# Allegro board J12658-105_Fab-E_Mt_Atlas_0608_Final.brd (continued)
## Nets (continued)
GND: C1.2(B) C2.2(B) C3.2(B) C4.2(B) C5.2(B) C6.2(B) C7.2(B) C8.2(B) C9.2(B) C10.2(B) C11.2(B) C12.2(B) C13.2(B) C14.2(B) C15.2(B) C16.2(B) C17.2(B) C18.2(B) C19.2(B) C20.2(B) C21.2(B) C22.2(B) C23.2(B) C24.2(B) C25.2(B) C26.2(B) C27.2(B) C28.2(B) C29.2(B) C30.2(B) C31.2(B) C32.2(B) C33.2(B) C34.2(B) C35.2(B) C36.2(B) C37.2(B) C38.2(B) C39.2(B) C40.2(B) C41.2(B) C42.2(B) C43.2(B) C44.2(B) C45.2(B) C46.2(B) C47.2(B) C48.2(B) C49.2(B) C50.2(B) C51.2(B) C52.2(B) C53.2(B) C54.2(B) C55.2(B) C56.2(B) C57.2(B) C58.2(B) C59.2(B) C60.2(B) C61.2(B) C62.2(B) C63.2(B) C64.2(B) C65.2(B) C66.2(B) C67.2(B) C68.2(B) C69.2(B) C70.2(B) C71.2(B) C72.2(B) C73.2(B) C74.2(B) C75.2(B) C76.2(B) C77.2(B) C78.2(B) C79.2(B) C80.2(B) C81.2(B) C82.2(B) C83.2(B) C84.2(B) C85.2(B) C86.2(B) C87.2(B) C88.2(B) C89.2(B) C90.2(B) C91.2(B) C92.2(B) C93.2(B) C94.2(B) C95.2(B) C96.2(B) C97.2(B) C98.2(B) C99.2(B) C100.2(B) C101.2(B) C102.2(B) C103.2(B) C104.2(B) C105.2(B) FL1.2(GND0) FL1.3(GND1) FL1.5(GND2) HW1.1(GND) HW1.2(GND1) HW1.3(GND2) HW1.4(GND3) HW1.5(GND4) HW1.6(GND5) HW1.7(GND6) HW1.8(GND7) J1.5 J1.6(SHIELD6) J1.7(SHIELD7) J1.8(SHIELD8) J1.9(SHIELD9) J1.10(SHIELD10) J1.11(SHIELD111) J2.5 J2.6(SHIELD6) J2.7(SHIELD7) J2.8(SHIELD8) J2.9(SHIELD9) J2.10(SHIELD10) J2.11(SHIELD111) J4.1(IO1) J6.3 J8.4 J9.6 J9.7 J10.3 J10.5 J10.9 J13.2(SHLD1) J13.3(SHLD2) J14.11 J14.12 J14.33 J14.40 J15.17 J15.18 J15.43 J15.44 J20.1 J21.1 MH1.1 MH2.1 MH3.1 MH4.1 Q1.2 Q2.2 Q4.2 Q5.2 R1.2(B) R4.2(B) R6.2(B) R11.2(B) R17.2(B) R61.2(B) R87.2(B) R91.2(B) R97.2(B) R102.2(B) R110.2(B) R122.2(B) R123.2(B) R130.2(B) R141.2(B) R142.2(B) R144.2(B) R146.2(B) R148.2(B) R151.2(B) R167.2(B) R171.2(B) R188.2(B) R192.2(B) R199.2(B) R204.2(B) R257.2(B) R262.1(A) R274.2(B) R276.2(B) R280.2(B) R283.2(B) R284.2(B) RF1.2 RF1.5 RF1.6 S1.1 SW1.1 SW2.1 SW4.5 U1.5(GND) U1.7(THPAD) U2.5(GND) U2.7(THPAD) U3.2(GND) U4.2(GND) U5.2(GND) U6.2(VSS) U7.B1(GND) U8.8(GND) U9.10(GND1) U9.11(GND2) U10.2(GND) U10.3(A0) U10.7(EP) U11.9(GND_1) U11.18(GND_2) U11.25(GND_3) U11.34(GND_4) U11.45(AGND) U11.47(TEST) U12.1(A0) U12.2(A1) U12.3(A2) U12.4(VSS) U12.7(WP) U12.9(EP) U13.10(GND1) U13.11(GND2) U14.6(GNDIO) U14.7(GND) U15.4(GND) U15.9(SLUG) U16.2(GND) U16.5(PAD) U17.10(GND1) U17.11(GND2) U18.8(GND) U19.8(GND) U19.15(OE*) U20.8(GND) U20.15(OE*) U21.2(GND) U22.A1(VSS) U22.A12(VSS1) U22.E7(VSS2) U22.F7(VSS3) U22.F8(VSS_RTC) U22.G6(VSS_IO_AON1) U22.G7(VSS4) U22.H6(VSS_GNDSENSE_ESR1) U22.H8(VSS5) U22.J2(VSS_GNDSENSE_ESR2) U22.J3(VSS_AVS_ESR2) U22.J6(VSS_AVS_ESR1) U22.J8(VSS_AVS_ESR3) U22.J9(VSS6) U22.J10(VSS_IO_AON) U22.J11(VSS_USB) U22.J12(VSS_PLL) U22.L3(VSS_GNDSENSE_OPM) U22.L8(VSS_AVSS_CMP) U22.M1(VSS7) U22.M7(VSS_GNDSENSE_ESR3) U22.M9(VSS_AVSS_CMP1) U22.M12(VSS8) U23.8(GND) U23.15(OE*) U24.2(GND) U25.8(GND) U25.15(OE*) U26.3(GND) U27.2(GND) U28.8(GND) U28.15(OE*) U29.29(PAD) U30.1(GND1) U30.2(GND2) U30.13(GND13) U30.25(GND25) U30.42(GND42) U31.3(GND) U31.5(DIE) U32.4(GND) U33.2(GND) U36.2(GND) U37.2(GND) U38.2(GND) U39.3(GND) U40.3(PGND) U40.9(GND) U40.11(THPAD) Y2.2(GND0) Y2.4(GND1) Y4.2(GND0) Y4.4(GND1)
VBAT_SOC: C27.1(A) C30.1(A) C83.1(A) FB11.2(B) U22.K2(VCC_BATT_ESR2_3P7) U22.L1(VCC_BATT_OPM_3P7) U22.L2(VCC_BATT_ESR3_3P7) U22.M2(VCC_BATT_ESR1_3P7)
VCC_ADC: C23.1(A) C77.1(A) FB16.2(B) U22.M10(VCC_ADC_3P3)
VCC_AON_1P8: C82.1(A) C92.1(A) C93.1(A) U22.H4(VCC_AON_1P8) U22.H5(VCC_AON_1P8_1) U22.J4(VCC_RTC_1P8) U22.J5(VCC_SRAM_1P8) U27.5(OUT)
VCC_AON_EN: R215.2(B) U27.3(EN)
VCC_ARD_USB_5V: D6.1(CATHODE) D7.1(CATHODE) FB12.1(A) J5.1
VCC_AVD_OPM_2P6: C85.1(A) C88.1(A) U22.J1(VCCOUT_AVD_OPM_2P6) U22.K1(VCC_AVD_OPM_2P6)
VCC_CMP: C24.1(A) C78.1(A) R64.1(A) R272.2(B) U22.M8(VCC_CMP_3P3)
VCC_EX_HOST_1P8: C9.1(A) FB8.2(B) R10.1(A)
VCC_EX_PLT_1P8: C86.1(A) FB9.2(B) U8.3(D1)
VCC_EX_PLT_3P3: C76.1(A) FB7.2(B) R64.2(B) U18.3(D1)
VCC_HOST_1P8: C20.1(A) C81.1(A) FB8.1(A) L4.2 R5.1(A) R213.1(A) U22.H7(VCC_PLL_1P8) U22.J7(VCC_HOST_1P8) U22.K6(VCCOUT_HOST_1P8) U22.K7(VCC_HOST_1P8_1) U22.L6(VCC_VSENSE_ESR3) U22.L7(VCC_HOST_1P8_2)
VCC_HOST_1P8_IND: L4.1 U22.M6(VCCOUT_ESR3_1P8)
VCC_IO: C26.1(A) C28.1(A) C29.1(A) C60.1(A) C64.1(A) C67.1(A) C68.1(A) C70.1(A) C73.1(A) C80.1(A) C89.1(A) FB6.1(A) FB14.1(A) FB15.1(A) J10.1 R52.1(A) R66.2(B) R129.1(A) R134.1(A) R137.1(A) R150.1(A) R152.1(A) R153.1(A) R157.1(A) R159.1(A) R163.1(A) R165.1(A) R170.1(A) R172.1(A) R173.1(A) R174.1(A) R175.1(A) R176.1(A) R177.1(A) R178.1(A) R179.1(A) R180.1(A) R181.1(A) R182.1(A) R185.1(A) R187.1(A) R189.1(A) R190.1(A) R191.1(A) R193.1(A) R194.1(A) R197.1(A) R200.1(A) R201.1(A) R202.1(A) R203.1(A) R205.1(A) R206.1(A) R207.1(A) R209.1(A) R210.1(A) R211.1(A) R212.1(A) R232.1(A) R237.1(A) R246.1(A) R249.1(A) R275.1(A) R277.1(A) R282.1(A) U9.2(VCCB) U10.1(VCC) U12.8(VCC) U13.2(VCCB) U15.8(VDD) U17.2(VCCB) U19.16(VCC) U20.16(VCC) U21.5(VIN) U23.16(VCC) U25.16(VCC) U28.16(VCC) U32.8(VCC) U33.5(VCC) U36.6(VCCB) U38.5(VCC)
VCC_IO_AON: C22.1(A) C79.1(A) C102.1(A) R57.2(B) U22.F6(VCC_IO_AON1) U22.G8(VCC_IO_AON2) U22.H10(VCC_IO_AON) U26.4(VDD)
VCC_PLT: FB16.1(A) R57.1(A) R66.1(A) U8.6(S1) U18.6(S1)
VCC_PLT_1P8: C21.1(A) C87.1(A) FB9.1(A) L6.2 U22.K4(VCCOUT_QLR2_1P8) U22.L4(VCC_VSENSE_ESR2)
VCC_PLT_1P8_IND: L6.1 U22.M4(VCCOUT_ESR2_1P8)
VCC_PLT_3P3: C19.1(A) C63.1(A) FB7.1(A) L5.2 U22.K5(VCCOUT_QLR1_3P3) U22.L5(VCC_VSENSE_ESR1)
VCC_PLT_3P3_IND: L5.1 U22.M5(VCCOUT_ESR1_3P3)
VCC_RADIO: C31.1(A) FB15.2(B) R84.1(A) R88.1(A) R99.1(A) R100.1(A) R101.1(A) R106.1(A) R107.1(A) R113.1(A) R114.1(A)
VCC_RST_GEN: R125.2(B) U31.4(VCC)
VCC_USB_3P3: C17.1(A) C18.1(A) C74.1(A) R278.1(A) U16.1(VOUT) U22.L12(VCC_USB_3P3)
VCCOUT_AON_1P8: C25.1(A) C84.1(A) R215.1(A) U22.M3(VCCOUT_AON_1P8)
VDD_ARDUINO: C44.1(A) C46.1(A) FB10.1(A) R126.1(A) R272.1(A) U1.1(OUT)
VDD_ARDUINO_EN: R124.2(B) U1.4(EN)
VDD_ARDUINO_FB: R123.1(A) R126.2(B) U1.3(VSET_FB)
VDD_HDR: C47.1(A) C49.1(A) J14.1 J14.2 J14.23 J14.26 J14.49 J14.50 J15.1 J15.2 J15.29 J15.34 R132.1(A) U2.1(OUT)
VDD_HDR_EN: R131.2(B) U2.4(EN)
VDD_HDR_FB: R130.1(A) R132.2(B) R133.1(A) U2.3(VSET_FB)
VDD_IMU: C14.1(A) C15.1(A) FB6.2(B) R24.1(A) R28.1(A) U14.5(VDDIO) U14.8(VDD)
VDD_USB: C8.1(A) R273.1(A) U7.A1(VOUT)
VDD_USB_EN: C5.1(A) R10.2(B) U7.B2(ON)
VDD_USB_R: C98.1(A) R33.1(A) R273.2(B) U16.4(VIN)
15_4_GPIO0: R97.1(A) U29.10(GPIO0)
15_4_GPIO1: R83.2(B) R84.2(B) U29.9(GPIO1)
15_4_GPIO2: R98.2(B) R99.2(B) U29.7(GPIO2)
15_4_GPIO3: R85.2(B) R100.2(B) U29.6(GPIO3)
15_4_GPIO4: R86.2(B) R101.2(B) U29.5(GPIO4)
15_4_GPIO5: R87.1(A) U29.4(GPIO5)
15_4_RESET_N: R108.1(A) U32.3(2Y)
15_4_RESET_N_R: R108.2(B) U29.25(RESET*)
15_4_XIN: C40.1(A) U29.13(XOSC_Q1) Y4.3
15_4_XOUT: C37.1(A) U29.12(XOSC_Q2) Y4.1
A_3P3V: FB10.2(B) J9.4
A_5P0V: FB12.2(B) J9.5
A_VIN: FB13.2(B) J9.8
ADC_AGND: R192.1(A) U22.L10(VSS_ADC_AGND)
AMBIENT_INT_N: R150.2(B) U10.4(INT*)
AP_COMP_AREF: C75.1(A) R169.2(B) R170.2(B) R171.1(A) U22.H9(COMP_AREF)
AP_GPIO0_ADC0_SPI_S_CS_N: R178.2(B) R258.2(B) U22.D12(GPIO_0_AIN_0_SPI_S_CS_B)
AP_GPIO0_ADC0_SPI_S_CS_N_R_HDR: J15.42 R258.1(A)
AP_GPIO1_ADC1_SPI_S_MISO: R213.2(B) R242.2(B) U22.E10(GPIO_1_AIN_1_SPI_S_MISO) U28.13(4B2)
AP_GPIO1_ADC1_SPI_S_MISO_HDR: J15.38 R242.1(A)
AP_GPIO2_ADC2_SPI_S_SCK: R236.2(B) U22.E11(GPIO_2_AIN_2_SPI_S_SCK)
AP_GPIO2_ADC2_SPI_S_SCK_HDR: J15.36 R236.1(A)
AP_GPIO3_ADC3_SPI_S_MOSI: R251.2(B) U22.E12(GPIO_3_AIN_3_SPI_S_MOSI)
AP_GPIO3_ADC3_SPI_S_MOSI_HDR: J15.40 R251.1(A)
AP_GPIO4_ADC4: R38.1(A) R83.1(A) U22.F9(GPIO_4_AIN_4)
AP_GPIO4_ADC4_HDR: J14.13 R38.2(B)
AP_GPIO5_ADC5: R44.1(A) R98.1(A) U22.F10(GPIO_5_AIN_5)
AP_GPIO5_ADC5_HDR: J14.15 R44.2(B)
AP_GPIO6_ADC6: U22.L9(GPIO_6_AIN_6) U38.4(A)
AP_GPIO6_ADC6_HDR: J14.17 R47.2(B)
AP_GPIO6_ADC6_MUX: R47.1(A) R85.1(A) U38.1(B2)
AP_GPIO7_ADC7: R33.2(B) R199.1(A) R261.1(A) U22.K8(GPIO_7_AIN_7)
AP_GPIO7_ADC7_HDR: J14.47 R261.2(B)
AP_GPIO8_SPI1_M_SCK: R63.2(B) R96.1(A) R229.2(B) U22.D6(GPIO_8_SPI1_M_SCK)
AP_GPIO8_SPI1_M_SCK_BLE: R229.1(A) U30.12(P0.29/SCK)
AP_GPIO8_SPI1_M_SCK_HDR: J15.20 R63.1(A)
AP_GPIO8_SPI1_M_SCK_R: R96.2(B) U29.28(SCLK)
AP_GPIO9_SPI1_M_MISO: R73.2(B) R92.1(A) R228.2(B) U22.B6(GPIO_9_SPI1_M_MISO)
AP_GPIO9_SPI1_M_MISO_BLE: R228.1(A) U30.11(P0.28/MISO)
AP_GPIO9_SPI1_M_MISO_HDR: J15.22 R73.1(A)
AP_GPIO9_SPI1_M_MISO_R: R91.1(A) R92.2(B) U29.1(SO)
AP_GPIO10_SPI1_M_MOSI: R77.2(B) R90.1(A) R245.2(B) U22.A6(GPIO_10_SPI1_M_MOSI)
AP_GPIO10_SPI1_M_MOSI_BLE: R245.1(A) U30.8(P0.25/MOSI)
AP_GPIO10_SPI1_M_MOSI_HDR: J15.24 R77.1(A)
AP_GPIO10_SPI1_M_MOSI_R: R90.2(B) U29.2(SI)
AP_GPIO11_SPI1_M_CS0_N: R81.2(B) R89.1(A) R211.2(B) U22.C6(GPIO_11_SPI1_M_CS_B_0)
AP_GPIO11_SPI1_M_CS0_N_HDR: J15.26 R81.1(A)
AP_GPIO11_SPI1_M_CS0_N_R: R88.2(B) R89.2(B) U29.3(CS*)
AP_GPIO12_SPI1_M_CS1_N: R205.2(B) R216.2(B) R250.2(B) R263.1(A) U22.B5(GPIO_12_SPI1_M_CS_B_1)
AP_GPIO12_SPI1_M_CS1_N_BLE: R250.1(A) U30.7(P0.24/SS)
AP_GPIO12_SPI1_M_CS1_N_HDR: J15.28 R216.1(A)
AP_GPIO13_SPI1_M_CS2_N: R206.2(B) R214.1(A) R219.2(B) U22.A5(GPIO_13_SPI1_M_CS_B_2)
AP_GPIO13_SPI1_M_CS2_N_HDR: J15.30 R219.1(A)
AP_GPIO14_SPI1_M_CS3_N: C104.1(A) R135.2(B) R210.2(B) R222.2(B) U22.D5(GPIO_14_SPI1_M_CS_B_3)
AP_GPIO14_SPI1_M_CS3_N_HDR: J15.32 R222.1(A)
AP_GPIO15_I2S_RXD: R67.2(B) U22.C5(GPIO_15_I2S_RXD) U25.3(1B2)
AP_GPIO15_I2S_RXD_HDR: J14.28 R67.1(A)
AP_GPIO16_I2S_RSCK: R80.2(B) U22.B4(GPIO_16_I2S_RSCK) U28.3(1B2)
AP_GPIO16_I2S_RSCK_HDR: J14.30 R80.1(A)
AP_GPIO17_I2S_RWS: R94.2(B) U22.D4(GPIO_17_I2S_RWS) U25.6(2B2)
AP_GPIO17_I2S_RWS_HDR: J14.32 R94.1(A)
AP_GPIO18_I2S_TSCK: R218.2(B) U22.A4(GPIO_18_I2S_TSCK) U28.6(2B2)
AP_GPIO18_I2S_TSCK_HDR: J14.34 R218.1(A)
AP_GPIO19_I2S_TWS: R224.2(B) U22.C4(GPIO_19_I2S_TWS) U28.10(3B2)
AP_GPIO19_I2S_TWS_HDR: J14.36 R224.1(A)
AP_GPIO20_I2S_TXD: R233.2(B) U22.B3(GPIO_20_I2S_TXD) U25.10(3B2)
AP_GPIO20_I2S_TXD_HDR: J14.38 R233.1(A)
AP_GPIO21_SPI0_M_SCK: R20.2(B) U15.6(CLK) U22.A3(GPIO_21_SPI0_M_SCK) U23.13(4B2)
AP_GPIO21_SPI0_M_SCK_HDR: J15.4 R20.1(A)
AP_GPIO22_SPI0_M_MISO: R27.2(B) U15.2(DO/1O1) U22.C3(GPIO_22_SPI0_M_MISO) U23.10(3B2)
AP_GPIO22_SPI0_M_MISO_HDR: J15.6 R27.1(A)
AP_GPIO23_SPI0_M_MOSI: R35.2(B) U15.5(IO0/DI) U22.D3(GPIO_23_SPI0_M_MOSI) U23.6(2B2)
AP_GPIO23_SPI0_M_MOSI_HDR: J15.8 R35.1(A)
AP_GPIO24_SPI0_M_CS0_N: R39.2(B) R159.2(B) U15.1(CE*) U22.E4(GPIO_24_SPI0_M_CS_B_0)
AP_GPIO24_SPI0_M_CS0_N_HDR: J15.10 R39.1(A)
AP_GPIO25_SPI0_M_CS1_N: Q4.1 R43.2(B) R209.2(B) U22.E3(GPIO_25_SPI0_M_CS_B_1)
AP_GPIO25_SPI0_M_CS1_N_HDR: J15.12 R43.1(A)
AP_GPIO26_SPI0_M_CS2_N: Q5.1 R48.2(B) R212.2(B) U22.B2(GPIO_26_SPI0_M_CS_B_2)
AP_GPIO26_SPI0_M_CS2_N_HDR: J15.14 R48.1(A)
AP_GPIO27_SPI0_M_CS3_N: R207.2(B) U22.A2(GPIO_27_SPI0_M_CS_B_3) U33.4(A)
AP_GPIO27_SPI0_M_CS3_N_HDR: J15.16 R54.1(A)
AP_GPIO27_SPI0_M_CS3_N_MUX: R54.2(B) U23.3(1B2) U33.1(B2)
AP_GPIO28: R61.1(A) U16.3(EN) U22.C2(GPIO_28)
AP_GPIO_AON0: R105.1(A) R221.1(A) U22.F3(GPIO_AON_0)
AP_GPIO_AON0_HDR: J14.35 R221.2(B)
AP_GPIO_AON0_R: R102.1(A) R105.2(B) R106.2(B) U29.26(VREG_EN)
AP_GPIO_AON1: R226.1(A) U22.F5(GPIO_AON_1) U32.6(2B)
AP_GPIO_AON1_HDR: J14.37 R226.2(B)
AP_GPIO_AON2: R235.1(A) U22.F4(GPIO_AON_2) U32.1(1A)
AP_GPIO_AON2_HDR: J14.39 R235.2(B)
AP_GPIO_AON3: R183.1(A) R240.1(A) U22.F2(GPIO_AON_3)
AP_GPIO_AON3_HDR: J14.41 R240.2(B)
AP_GPIO_AON4: C105.1(A) R136.2(B) R247.1(A) U22.F1(GPIO_AON_4)
AP_GPIO_AON4_HDR: J14.43 R247.2(B)
AP_GPIO_AON5: R195.1(A) R255.1(A) U22.E6(GPIO_AON_5)
AP_GPIO_AON5_HDR: J14.45 R255.2(B)
AP_GPIO_SS0_ADC8_UART1_CTS_N: R174.2(B) U20.9(3A) U22.F11(GPIO_SS_0_AIN_8_UART1_CTS)
AP_GPIO_SS1_ADC9_UART1_RTS_N: R175.2(B) U20.12(4A) U22.F12(GPIO_SS_1_AIN_9_UART1_RTS)
AP_GPIO_SS2_ADC10: R34.2(B) R225.1(A) U22.G9(GPIO_SS_2_AIN_10)
AP_GPIO_SS2_ADC10_HDR: J14.14 R34.1(A)
AP_GPIO_SS3_ADC11: R40.2(B) R234.1(A) U22.G10(GPIO_SS_3_AIN_11)
AP_GPIO_SS3_ADC11_HDR: J14.16 R40.1(A)
AP_GPIO_SS4_ADC12: R45.2(B) R156.2(B) R162.2(B) U22.G11(GPIO_SS_4_AIN_12)
AP_GPIO_SS4_ADC12_HDR: J14.18 R45.1(A)
AP_GPIO_SS5_ADC13: R53.2(B) R127.1(A) U22.G12(GPIO_SS_5_AIN_13)
AP_GPIO_SS5_ADC13_HDR: J14.20 R53.1(A)
AP_GPIO_SS6_ADC14: R59.2(B) R238.1(A) U22.K10(GPIO_SS_6_AIN_14)
AP_GPIO_SS6_ADC14_HDR: J14.22 R59.1(A)
AP_GPIO_SS7_ADC15: R65.2(B) R248.1(A) U22.K9(GPIO_SS_7_AIN_15)
AP_GPIO_SS7_ADC15_HDR: J14.24 R65.1(A)
AP_GPIO_SS8_ADC16_UART1_TXD: R172.2(B) U20.4(1A) U22.H11(GPIO_SS_8_AIN_16_UART1_TX)
AP_GPIO_SS9_ADC17_UART1_RXD: R173.2(B) U20.7(2A) U22.H12(GPIO_SS_9_AIN_17_UART1_RX)
AP_GPIO_SS10_PWM0: R70.1(A) U22.D2(GPIO_SS_10_PWM_0) U28.11(3B1)
AP_GPIO_SS10_PWM0_HDR: J14.25 R70.2(B)
AP_GPIO_SS11_PWM1: R74.1(A) U22.B1(GPIO_SS_11_PWM_1) U28.5(2B1)
AP_GPIO_SS11_PWM1_HDR: J14.27 R74.2(B)
AP_GPIO_SS12_PWM2: R76.1(A) U22.E2(GPIO_SS_12_PWM_2) U28.14(4B1)
AP_GPIO_SS12_PWM2_HDR: J14.29 R76.2(B)
AP_GPIO_SS13_PWM3: R82.1(A) U22.C1(GPIO_SS_13_PWM_3) U28.2(1B1)
AP_GPIO_SS13_PWM3_HDR: J14.31 R82.2(B)
AP_GPIO_SS14_PLT_CLK_0: R49.1(A) U22.D1(GPIO_SS_14_PLT_CLK_0) U25.11(3B1)
AP_GPIO_SS14_PLT_CLK_0_HDR: J14.19 R49.2(B)
AP_GPIO_SS15_PLT_CLK_1: R55.1(A) U22.E1(GPIO_SS_15_PLT_CLK_1) U25.14(4B1)
AP_GPIO_SS15_PLT_CLK_1_HDR: J14.21 R55.2(B)
AP_I2C0_SCL: R153.2(B) R198.1(A) R220.1(A) R230.2(B) R265.1(A) U12.6(SCL) U22.C12(I2C0_SCL)
AP_I2C0_SCL_AMBIENT: R265.2(B) U10.5(SCL)
AP_I2C0_SCL_BLE: R230.1(A) U30.24(P0.07/SCL)
AP_I2C0_SCL_HDR: J15.31 R220.2(B)
AP_I2C0_SCL_TEMP: R198.2(B) U21.1(SCL)
AP_I2C0_SDA: R157.2(B) R196.1(A) R223.1(A) R227.2(B) R264.1(A) U12.5(SDA) U22.B12(I2C0_SDA)
AP_I2C0_SDA_AMBIENT: R264.2(B) U10.6(SDA)
AP_I2C0_SDA_BLE: R227.1(A) U30.16(P0.30/SDA)
AP_I2C0_SDA_HDR: J15.33 R223.2(B)
AP_I2C0_SDA_TEMP: R196.2(B) U21.6(SDA)
AP_I2C0_SS_SCL: R181.2(B) R231.1(A) U22.B11(I2C0_SS_SCL)
AP_I2C0_SS_SCL_HDR: J15.35 R231.2(B)
AP_I2C0_SS_SDA: R185.2(B) R241.1(A) U22.A11(I2C0_SS_SDA)
AP_I2C1_SCL: R179.2(B) R244.1(A) U19.6(2B2) U22.D11(I2C1_SCL)
AP_I2C1_SCL_HDR: J15.39 R244.2(B)
AP_I2C1_SDA: R182.2(B) R256.1(A) U19.3(1B2) U22.C11(I2C1_SDA)
AP_I2C1_SDA_HDR: J15.41 R256.2(B)
AP_I2C1_SS_SCL: R30.1(A) R116.2(B) R187.2(B) U19.5(2B1) U22.D10(I2C1_SS_SCL)
AP_I2C1_SS_SCL_HDR: J14.44 R116.1(A)
AP_I2C1_SS_SCL_IMU: R28.2(B) R30.2(B) U14.3(ASCX)
AP_I2C1_SS_SDA: R25.1(A) R112.2(B) R191.2(B) U19.2(1B1) U22.C10(I2C1_SS_SDA)
AP_I2C1_SS_SDA_HDR: J14.42 R112.1(A)
AP_I2C1_SS_SDA_IMU: R24.2(B) R25.2(B) U14.2(ASDX)
AP_JTAG_TCK: R274.1(A) U13.15(1B1) U22.G2(TCK)
AP_JTAG_TDI: R129.2(B) U13.14(1B2) U22.G4(TDI)
AP_JTAG_TDO: R277.2(B) U17.13(2B1) U22.H3(TDO)
AP_JTAG_TMS: R275.2(B) U13.13(2B1) U22.G3(TMS)
AP_JTAG_TRST_N: R276.1(A) U13.12(2B2) U22.G1(TRST_B)
AP_PWRGOOD: U22.G5(VCC_HOST_1P8_PG) U26.1(DOUT)
AP_PWRGOOD_SENSE: C101.1(A) R5.2(B) U26.2(SENSE)
AP_RESET_N: R281.1(A) U32.2(1B) U32.5(2A) U36.4(B)
AP_RESET_N_R: R281.2(B) U22.E5(RST_B)
AP_RESET_N_VSYS: U31.1(N_RST) U36.3(A)
AP_SPI0_SS_CS0_N: R41.1(A) R152.2(B) U14.12(CSB) U22.A9(SPI0_SS_CS_B_0)
AP_SPI0_SS_CS0_N_HDR: J15.9 R41.2(B)
AP_SPI0_SS_CS1_N: R46.1(A) R180.2(B) U22.D9(SPI0_SS_CS_B_1)
AP_SPI0_SS_CS1_N_HDR: J15.11 R46.2(B)
AP_SPI0_SS_CS2_N_GPIO29: R50.1(A) R86.1(A) R193.2(B) U22.B9(SPI0_SS_CS_B_2_GPIO_29)
AP_SPI0_SS_CS2_N_GPIO29_HDR: J15.13 R50.2(B)
AP_SPI0_SS_CS3_N_GPIO30: R56.1(A) R194.2(B) U22.C8(SPI0_SS_CS_B_3_GPIO_30) U25.13(4B2)
AP_SPI0_SS_CS3_N_GPIO30_HDR: J15.15 R56.2(B)
AP_SPI0_SS_MISO: R32.1(A) U14.1(SDO) U22.A10(SPI0_SS_MISO)
AP_SPI0_SS_MISO_HDR: J15.5 R32.2(B)
AP_SPI0_SS_MOSI: R37.1(A) U14.14(SDX) U22.B10(SPI0_SS_MOSI)
AP_SPI0_SS_MOSI_HDR: J15.7 R37.2(B)
AP_SPI0_SS_SCK: R23.1(A) U14.13(SCX) U22.C9(SPI0_SS_SCK)
AP_SPI0_SS_SCK_HDR: J15.3 R23.2(B)
AP_SPI1_SS_CS0_N: R93.1(A) R201.2(B) U22.C7(SPI1_SS_CS_B_0) U23.2(1B1)
AP_SPI1_SS_CS0_N_HDR: J15.25 R93.2(B)
AP_SPI1_SS_CS1_N: R200.2(B) R217.1(A) U22.A7(SPI1_SS_CS_B_1)
AP_SPI1_SS_CS1_N_HDR: J15.27 R217.2(B)
AP_SPI1_SS_CS2_N_UART0_CTS_N: R19.1(A) R190.2(B) R266.1(A) U22.D8(SPI1_SS_CS_B_2_UART0_CTS_B)
AP_SPI1_SS_CS2_N_UART0_CTS_N_BLE: R266.2(B) U30.26(P0.08)
AP_SPI1_SS_CS2_N_UART0_CTS_N_HDR: J14.7 R19.2(B)
AP_SPI1_SS_CS3_N_UART0_RTS_N: R22.1(A) R202.2(B) R267.1(A) U22.D7(SPI1_SS_CS_B_3_UART0_RTS_B)
AP_SPI1_SS_CS3_N_UART0_RTS_N_BLE: R267.2(B) U30.28(P0.10)
AP_SPI1_SS_CS3_N_UART0_RTS_N_HDR: J14.9 R22.2(B)
AP_SPI1_SS_MISO: R75.1(A) U22.A8(SPI1_SS_MISO) U23.11(3B1)
AP_SPI1_SS_MISO_HDR: J15.21 R75.2(B)
AP_SPI1_SS_MOSI: R79.1(A) U22.B7(SPI1_SS_MOSI) U23.5(2B1)
AP_SPI1_SS_MOSI_HDR: J15.23 R79.2(B)
AP_SPI1_SS_SCK: R69.1(A) U22.B8(SPI1_SS_SCK) U23.14(4B1)
AP_SPI1_SS_SCK_HDR: J15.19 R69.2(B)
AP_UART0_RXD_ADC18: R16.1(A) R177.2(B) R239.2(B) U22.E8(UART0_RXD_AIN_18)
AP_UART0_RXD_ADC18_BLE: R239.1(A) U30.27(P0.09/TX)
AP_UART0_RXD_ADC18_HDR: J14.5 R16.2(B)
AP_UART0_TXD_GPIO31: R12.1(A) R176.2(B) R243.2(B) U22.E9(UART0_TXD_GPIO_31)
AP_UART0_TXD_GPIO31_BLE: R243.1(A) U30.29(P0.11/RX)
AP_UART0_TXD_GPIO31_HDR: J14.3 R12.2(B)
AP_USB_5V: C52.1(A) C53.1(A) D7.2(ANODE) FB2.1(A) R9.1(A)
AP_USB_5V_R: C4.1(A) R9.2(B) U7.A2(VIN)
AP_USB_DN: L1.2(OUT_1) U22.M11(USB_DN)
AP_USB_DP: L1.3(IN_2) R278.2(B) U22.L11(USB_DP)
AP_USB_ID: J1.4 U34.1
AP_VBUS: C1.1(A) D2.1(A) FB2.2(B) J1.1 R11.1(A) U3.5(VCC)
ARD_A0: J12.1 R225.2(B)
ARD_A1: J12.2 R234.2(B)
ARD_A2: J12.3 R238.2(B)
ARD_A3: J12.4 R248.2(B)
ARD_A4: J12.5 R254.2(B)
ARD_A4_SPARE: J8.2 R36.1(A)
ARD_A5: J12.6 R260.2(B)
ARD_A5_SPARE: J8.1 R29.1(A)
ARD_AREF: J8.3 R42.1(A)
ARD_D0: J11.1 R121.1(A)
ARD_D1: J11.2 R119.1(A)
ARD_D2: J11.3 R111.1(A)
ARD_D3: J11.4 R115.1(A)
ARD_D4: J11.5 R117.1(A)
ARD_D5: J11.6 R109.1(A)
ARD_D6: J11.7 R103.1(A)
ARD_D7: J11.8 R95.1(A)
ARD_D8: J8.10 R78.1(A)
ARD_D9: J8.9 R72.1(A)
ARD_D10: J8.8 R68.1(A)
ARD_D11: J8.7 R62.1(A)
ARD_D12: J8.6 R58.1(A)
ARD_D13: J8.5 R51.1(A)
ARD_IOREF: J9.2 R52.2(B)
ARD_RESET_N: R60.1(A) U32.7(1Y)
ARD_RESET_N_R: J9.3 R60.2(B) R259.2(B)
ARD_RESET_N_R_HDR: J14.48 R259.1(A)
ARDUINO_A4: R36.2(B) R254.1(A) U19.4(1A)
ARDUINO_A5: R29.2(B) R260.1(A) U19.7(2A)
ARDUINO_CTS: R21.2(B) U20.11(3B1) U25.2(1B1)
ARDUINO_IO_0_UART_RXD: R18.2(B) R121.2(B) U20.5(2B1)
ARDUINO_IO_1_UART_TXD: R14.2(B) R119.2(B) U20.2(1B1)
ARDUINO_IO_2: R111.2(B) U25.7(2A)
ARDUINO_IO_3: R115.2(B) U28.4(1A)
ARDUINO_IO_4: R117.2(B) U25.4(1A)
ARDUINO_IO_5: R109.2(B) U28.7(2A)
ARDUINO_IO_6: R103.2(B) U28.9(3A)
ARDUINO_IO_7: R95.2(B) U25.9(3A)
ARDUINO_IO_8: R78.2(B) U25.12(4A)
ARDUINO_IO_9: R72.2(B) U28.12(4A)
ARDUINO_IO_10: R68.2(B) U23.4(1A)
ARDUINO_IO_11: R62.2(B) U23.7(2A)
ARDUINO_IO_12: R58.2(B) U23.9(3A)
ARDUINO_IO_13: R51.2(B) U23.12(4A)
ARDUINO_RTS: R26.2(B) U20.14(4B1) U25.5(2B1)
ARDUINO_VIN: FB13.1(A) TP1.1(TP)
ATP_BLE_INT: R263.2(B) U30.32(P0.14)
BEST_OF_SUPPLY: C7.1(A) J5.2 R15.1(A) R143.1(A) U40.5(VIN)
BLE_ATP_INT: R195.2(B) U30.31(P0.13)
BLE_MUX_SEL: R214.2(B) R282.2(B) R283.1(A) U33.6(S) U38.6(S)
BLE_SWDCLK: J10.4 R269.1(A) U33.3(B1)
BLE_SWDCLK_R: R257.1(A) R269.2(B) U30.36(SWDCLK)
BLE_SWDIO: J10.2 R268.1(A) U38.3(B1)
BLE_SWDIO_R: R253.2(B) R268.2(B) U30.35(SWDIO/RESET)
BLE_VIN: C34.1(A) C94.1(A) FB14.2(B) R253.1(A) U30.3(AVDD) U30.14(VDD)
BLE_XIN: C36.1(A) U30.10(P0.27/XL1) Y5.2(B)
BLE_XOUT: C41.1(A) U30.9(P0.26/XL2) Y5.1(A)
CLK_HYB_32M_XTALI: R164.2(B) U22.K12(OSC32M_IN) Y2.3
CLK_HYB_32M_XTALO: R164.1(A) U22.K11(OSC32M_OUT) Y2.1
CLK_RTC_32K_XTALI: R71.2(B) U22.H2(OSC32K_IN) Y3.2(B)
CLK_RTC_32K_XTALO: R71.1(A) U22.H1(OSC32K_OUT) Y3.1(A)
D+PR: L1.4(OUT_2) U3.1(D+P)
D-PR: L1.1(IN_1) U3.3(D-P)
DM: J1.2 U3.4(D-)
DP: J1.3 U3.6(D+)
EE_CLK: R271.2(B) U6.4(CLK) U11.1(EESK)
EE_CS: R270.2(B) U6.5(CS) U11.48(EECS)
EE_DATA: R140.1(A) U6.3(DI) U11.2(EEDATA)
EE_DATA_R: R139.2(B) R140.2(B) U6.1(DO)
F_ACBUS2: TP4.1(TP) U11.12(ACBUS2)
F_ACBUS3: TP3.1(TP) U11.11(ACBUS3)
F_JTAG_3P3_M_RST: R31.2(B) R151.1(A) R208.2(B) U11.20(ADBUS4) U37.1(A)
F_JTAG_3P3_M_RST_INV: R184.2(B) R208.1(A) U17.6(1A1)
F_JTAG_3P3_M_RST_INV_R: R184.1(A) U37.4(Y*)
F_JTAG_OE_N: R160.1(A) U11.17(ADBUS6)
F_JTAG_OE_N_R: R158.2(B) R160.2(B) U39.1(A)
F_JTAG_TCK: U11.24(ADBUS0) U13.6(1A1)
F_JTAG_TDI: U11.23(ADBUS1) U13.7(1A2)
F_JTAG_TDO: U11.22(ADBUS2) U17.8(2A1)
F_JTAG_TMS: U11.21(ADBUS3) U13.8(2A1)
F_JTAG_TRST_N: R148.1(A) U11.15(ACBUS0) U13.9(2A2)
F_JTAG_XCVR_OE_N: R154.2(B) U13.1(1OE*) U13.16(2OE*) U17.1(1OE*) U17.16(2OE*) U39.4(Y)
F_PWREN_N: R166.1(A) R168.1(A) U11.41(PWREN_N)
F_UART_3P3_CTS: U9.9(2A2) U11.37(BDBUS3)
F_UART_3P3_RTS: U9.7(1A2) U11.38(BDBUS2)
F_UART_3P3_RX: U9.8(2A1) U11.39(BDBUS1)
F_UART_3P3_TX: U9.6(1A1) U11.40(BDBUS0)
F_UART_OE_N_R: R155.2(B) R166.2(B) U39.2(B)
F_UART_XCVR_OE_N_R: R167.1(A) R168.2(B) R285.2(B) U9.1(1OE*) U9.16(2OE*)
FT_D+P: L2.4(OUT_2) R8.1(A) U4.1(D+P)
FT_D-P: L2.1(IN_1) U4.3(D-P)
FTD_3P3: C57.1(A) C58.1(A) C66.1(A) C69.1(A) C71.1(A) C96.1(A) FB5.1(A) R31.1(A) R141.1(A) R145.1(A) R154.1(A) R155.1(A) R158.1(A) R161.1(A) R186.1(A) R285.1(A) U9.3(VCCA) U11.10(SI_WUA) U11.14(VCCIOA) U11.26(SI_WUB) U11.31(VCCIOB) U13.3(VCCA) U17.3(VCCA) U37.5(VCC) U39.5(VCC)
FTD_AVCC: C59.1(A) R147.2(B) U11.46(AVCC)
FTD_DM: J2.2 U4.4(D-)
FTD_DP: J2.3 U4.6(D+)
FTD_M_RST: R128.2(B) U17.15(1B1)
FTD_M_RST_R: Q1.1 R122.1(A) R128.1(A)
FTD_USB_5V: C3.1(A) C13.1(A) C50.1(A) C54.1(A) C61.1(A) C65.1(A) D6.2(ANODE) FB4.1(A) R138.1(A) R139.1(A) R147.1(A) R149.1(A) R270.1(A) R271.1(A) U5.1(IN) U6.6(VCC) U11.3(VCC_1) U11.42(VCC_2)
FTD_USB_ID: J2.4 U35.1
FTD_VBUS: C2.1(A) D1.1(A) FB4.2(B) J2.1 R6.1(A) U4.5(VCC)
FTDI_RESET_N: R149.2(B) U11.4(RESET_N)
FTDI_XIN: C16.1(A) U11.43(XTIN) Y1.1
FTDI_XOUT: C6.1(A) U11.44(XTOUT) Y1.3
GPIO25_LED: D4.1(A) R3.2(B)
GPIO25_LED_R: D4.2(C) Q4.3
GPIO26_LED: D3.1(A) R2.2(B)
GPIO26_LED_R: D3.2(C) Q5.3
IMU_INT1: R156.1(A) U14.4(INT1)
IMU_INT2: R162.1(A) U14.9(INT2)
JTAG_TDI_DIR: R161.2(B) U13.4(1DIR) U13.5(2DIR)
JTAG_TDO_DIR: R284.1(A) U17.5(2DIR)
M_RST_DIR: R186.2(B) U17.4(1DIR)
MUX_CTRL_1: R232.2(B) SW4.1 U23.1(S)
MUX_CTRL_2: R237.2(B) SW4.2 U25.1(S)
MUX_CTRL_3: R246.2(B) SW4.3 U28.1(S)
MUX_CTRL_4: R249.2(B) SW4.4 U19.1(S)
PB0_BTN: R136.1(A) R137.2(B) SW1.2
PB1_BTN: R134.2(B) R135.1(A) SW2.2
PLT_REG_EN: R262.2(B) U22.K3(PLT_REG_EN)
RESET_BTN: Q1.3 S1.2 U31.2(N_MR)
RF_1: RF1.4 U29.17(RF_P)
RF_2: RF1.3 U29.19(RF*)
RF_3: L7.1 RF1.1
RF_4: L7.2 L8.1(INA) R118.1(A)
RF_5: FL1.1(IN) L8.2(INB)
RF_6: FL1.4(OUT) L9.1(INA)
RF_ANT: C43.1(A) L10.2(INB) RF2.1(FEED1) RF2.3(FEED2)
RF_ANT_R: C42.1(A) L9.2(INB) L10.1(INA) R118.2(B) R120.1(A)
RF_EXT_ANT: J13.1(SIG) R120.2(B)
RSTOUT_N: R8.2(B) U11.5(RSTOUT_N)
TMP_I2C_ADDRESS: R203.2(B) R204.1(A) U21.4(ADD0)
UART1_CTS_FTD: U9.14(1B2) U20.10(3B2)
UART1_CTS_HDR_HDR: J14.8 R21.1(A)
UART1_RTS_FTD: U9.12(2B2) U20.13(4B2)
UART1_RTS_HDR_HDR: J14.10 R26.1(A)
UART1_RXD_FTD: U9.15(1B1) U20.6(2B2)
UART1_RXD_HDR_HDR: J14.6 R18.1(A)
UART1_TXD_FTD: U9.13(2B1) U20.3(1B2)
UART1_TXD_HDR_HDR: J14.4 R14.1(A)
UART_MUX_SEL: R183.2(B) R188.1(A) R189.2(B) U20.1(S)
UART_RX_DIR: R146.1(A) U9.5(2DIR)
UART_TX_DIR: R145.2(B) U9.4(1DIR)
UNNAMED_6_HDR2X22_I187_37: J15.37 R241.2(B)
UNNAMED_11_RES_I77_B: R197.2(B) U21.3(ALERT*)
UNNAMED_12_CAP_I18_A: C32.1(A) U29.27(DCOUPL)
UNNAMED_12_CC2520RHDT_I96_RBIAS: R110.1(A) U29.23(RBIAS)
UNNAMED_13_CAP_I46_A: C95.1(A) U30.41(DEC2)
UNNAMED_14_LED_I15_C: D2.2(C) R1.1(A)
UNNAMED_15_RES_I26_B: R163.2(B) U15.7(IO3/HOLD*)
UNNAMED_15_RES_I27_B: R165.2(B) U15.3(WP_N/IO2)
UNNAMED_17_FERRITE_I54_A: FB3.1(A) J3.3
UNNAMED_18_DMN1150UFB7B_I109_3: Q2.3 R133.2(B)
UNNAMED_18_RES_I145_B: J6.1 R7.2(B)
UNNAMED_19_CAP_I58_A: C62.1(A) U11.6(3V3OUT)
UNNAMED_19_CAP_I85_A: C51.1(A) FB5.2(B) U5.5(OUT)
UNNAMED_19_LED_I28_C: D1.2(C) R4.1(A)
UNNAMED_19_RES_I88_B: R138.2(B) U5.3(EN)
USB_FTD_DM: L2.2(OUT_1) U11.8(USBDM)
USB_FTD_DP: L2.3(IN_2) U11.7(USBDP)
V_BATT: F1.2(B) J4.2(IO2)
V_BATT_FUSE: D8.2(ANODE) F1.1(A)
V_BATT_FUSE_D: D8.1(CATHODE) FB3.2(B) J5.3
V_BB_3P8: C10.1(A) C11.1(A) C12.1(A) C56.1(A) J3.1 R2.1(A) R3.1(A) R13.1(A) U40.1(VOUT)
V_BB_EN: R15.2(B) U40.6(EN)
V_BB_FB: R13.2(B) R144.1(A) U40.10(FB)
V_BB_L1: L3.2 U40.4(L1)
V_BB_L2: L3.1 U40.2(L2)
V_BB_PS: R142.1(A) R143.2(B) U40.7(PS_SYNC)
V_BB_VINA: C55.1(A) U40.8(VINA)
VOLT_SEL: J6.2 Q2.1 U18.2(ON) U24.1(A)
VOLT_SEL_N: U8.2(ON) U24.4(Y*)
VSYS: C45.1(A) C48.1(A) C72.1(A) C90.1(A) C91.1(A) C99.1(A) C100.1(A) C103.1(A) FB1.1(A) FB11.1(A) R7.1(A) R124.1(A) R125.1(A) R131.1(A) R279.1(A) SW3.2(P2) U1.6(IN) U2.6(IN) U8.1(VDD) U18.1(VDD) U24.5(VCC) U27.1(IN) U36.1(VCCA) U36.5(DIR)
VSYS_ADC_SENSE: C97.1(A) R127.2(B) R279.2(B) R280.1(A)
VSYS_DISCH: R17.1(A) SW3.3(P3)
VSYS_SENSE: FB1.2(B) J3.2 SW3.1(P1)
XVREF: R42.2(B) R169.1(A) R252.2(B)
XVREF_HDR: J14.46 R252.1(A)

Pads without a net: J9 1; J10 6 7 8 10; RF2 2; U1 2; U2 2; U5 4; U8 7; U11 13 16 19 27 28 29 30 32 33 35 36; U14 10 11; U17 7 9 12 14; U18 7; U19 9 10 11 12 13 14; U24 3; U26 5; U27 4; U29 15 18 21; U30 4 5 6 15 17 18 19 20 21 22 23 30 33 34 37 38 39 40; U37 3; Y1 2 4

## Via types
v1: diameter 0.457, hole 0.203, TOP to BOTTOM, 1115 vias

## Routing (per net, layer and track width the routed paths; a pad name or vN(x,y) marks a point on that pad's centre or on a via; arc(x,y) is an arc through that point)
AVDD_A_RADIO: length 5.1
  TOP w0.254: U29.11 41.15,17.78 40.7,17.34 C35.1 R107.2 39.81,18.67 39.12,19.37 R104.2
AVDD_B_RADIO: length 3.5
  TOP w0.254: U29.16 43.32,14.75 42.74,14.16 C38.1 R113.2
AVDD_C_RADIO: length 9.1
  TOP w0.254: U29.24 v1(47.74,17.28) ; v1(46.29,14.54) 45.53,14.54 45.32,14.75 U29.20 ; v1(47.37,15.75) 47.37,16 47.09,16.28 U29.22
  TOP w0.381: v1(46.29,14.54) 46.61,14.54 C39.1 47.62,14.16 R114.2
  L3_SIG w0.508: v1(47.74,17.28) 47.74,16.12 v1(47.37,15.75) 47.37,15.62 v1(46.29,14.54)
DVDD_RADIO: length 3
  TOP w0.254: C33.1 R104.1 40.96,19.88 41.55,19.28 U29.8
GND: length 491.8
  TOP w0.127: U16.5 42.03,45.41 U16.2 42.56,45.73 v1(43.12,46.29)
  TOP w0.152: U26.3 45.66,48.01 C102.2
  TOP w0.203: v1(42.67,28.45) 42.83,28.61 U24.2 45.05,28.61 v1(45.09,28.57) ; U37.2 49.43,49.37 v1(49.4,49.34) ; v1(46.76,30.26) 47.31,30.26 47.37,30.2 U8.8 46.96,29.51 ; U3.2 34.2,67.23 34.12,67.31 v1(33.24,67.31) ; U4.2 47.92,67.03 47.76,67.18 v1(46.48,67.18) ; U13.10 33.73,58.17 ; v1(47.75,33.78) 47.37,33.4 U18.8 46.96,32.56 ; 33.46,58.23 33.33,58.09 U13.11 ; 27.11,49.14 U14.7 ; 26.61,49.14 U14.6
  TOP w0.254: v1(16.38,20.45) 16.57,20.64 J10.3 16.57,24.75 ; R61.2 40.64,47.8 ; R61.2 40.08,47.24 ; R61.2 41.6,47.24 v1(41.71,47.13) ; U14.6 26.61,50.54 v1(26.83,50.77) 27.11,50.49 U14.7 ; U22.H8 v1(34.98,41.97) ; RF1.6 42.59,12.37 v1(42.29,12.07) ; RF1.6 44.24,12.37 ; RF1.6 43.42,11.88 ; 66.83,16.03 65.25,14.45 ; C33.2 v1(38.42,20.76) R97.2 37.86,21.72 ; 40.11,48.78 U11.25 ; U11.25 40.11,51.48 40.14,51.51 v1(40.14,51.56) ; U11.25 39.67,49.97 ; v1(59.12,72.25) 59.12,72.26 59.18,72.33 U1.7 59.18,74.54 ; 24.18,35.03 U23.15 21.69,35.03 v1(21.46,34.8) ; v1(27.81,70.87) R1.2 27.25,71.69 ; 46.74,44.96 v1(46.74,44.32) ; U22.J2 v1(35.78,36.37) ; v1(33.27,24.51) 33.5,24.28 U25.15 ; C26.2 v1(53.85,34.04) ; 4.29,34.77 J15.18 5.87,34.77 ; 35.67,7.73 J20.1 34.18,6.24 ; R110.2 49.96,16.51 ; R110.2 49.4,17.07 ; R110.2 v1(49.4,15.68) ; 41.66,12.71 C38.2 41.91,13.02 v1(42.42,13.02) RF1.5 44.24,13.02 ; U20.15 21.69,47.22 v1(21.46,46.99) ; 10.87,61.26 11.13,61 11.13,60.67 U40.9 11.12,60 v1(11.62,59.5) U40.3 ; 10.87,61.26 C55.2 ; 10.87,61.26 10.43,61.26 9.93,61.77 R144.2 ; J10.9 20.38,24.75 ; J10.9 21.06,23.05 ; J10.9 20.38,21.15 ; U17.10 47.76,46.55 v1(47.56,46.35) 47.76,46.16 U17.11 ; 44.37,71.97 J2.6 45.17,71.07 ; 53.54,71.56 R4.2 ; R4.2 54.66,71.56 ; R4.2 v1(54.1,70.8) ; 24.94,73.96 J4.1 22.61,71.62 ; v1(23.09,30.14) 23.51,29.73 U28.8 ; 30.66,17.77 U30.13 30.11,19.42 C34.2 v1(30.86,19.43) ; U11.47 45.69,56.42 v1(45.4,56.71) ; C43.2 v1(43.24,5.46) ; U25.8 29.6,27.7 v1(29.21,27.3) ; U25.8 29.6,30.02 ; U25.8 29.14,28.83 ; FL1.2 v1(43.31,8.7) ; U11.9 41.61,57.07 v1(41.78,56.9) ; U22.M12 v1(38.54,45.53) ; U22.G7 v1(34.18,40.37) U22.G6 ; 66.04,66.26 S1.1 ; S1.1 v1(67.5,67.31) ; S1.1 66.04,68.36 ; S1.1 v1(64.77,67.31) ; 18.66,64.71 C5.2 v1(18.1,65.41) ; SW2.1 v1(43.43,62.23) ; SW2.1 44.44,60.96 ; SW2.1 42.43,60.96 ; R17.2 6.54,63.68 ; R17.2 7.23,62.93 ; R17.2 5.85,62.93 ; 41.26,30.04 C30.2 40.51,29.26 ; C27.2 41.26,31.31 ; R91.2 v1(48.13,25.65) ; v1(53.85,37.08) C23.2 53.09,37.64 ; U2.5 60.91,70.15 v1(60.96,70.1) ; 38.86,12.9 C40.2 38.42,13.46 v1(38.16,13.72) ; C35.2 38.42,17.34 v1(38.23,17.14) ; U28.8 23.05,28.83 ; U28.8 23.51,27.63 ; 37.02,69.8 C1.2 ; C1.2 37.02,70.92 ; C1.2 v1(37.72,70.36) ; 44.95,36.7 C21.2 44.39,37.26 ; U12.2 11.82,48.9 v1(11.49,48.58) 11.31,48.76 U12.1 10.86,49.44 ; 62.71,50.01 J14.11 64.29,51.59 ; Y4.4 40.26,16 v1(40.39,15.88) ; 64.29,23.65 62.71,22.07 ; U9.11 55.06,56.44 v1(54.86,56.64) 55.06,56.84 U9.10 ; U22.J3 v1(35.78,37.17) ; 42.37,34.23 C87.2 ; C87.2 42.93,33.67 ; C87.2 43.49,34.23 ; 37,47.57 Y2.2 37.74,48.27 ; v1(60.96,73.41) 60.93,73.43 U1.5 ; 34.85,49.36 Y2.4 35.6,50.06 ; 55.83,71.65 R130.2 55.14,71.09 v1(55.12,71.12) ; 18.6,8.57 SW4.5 17.21,7.18 ; 37.99,60.96 SW1.1 ; SW1.1 v1(38.99,62.29) ; SW1.1 39.99,60.96 ; J1.5 32.58,71.06 ; 33.1,17.72 C36.2 ; C36.2 33.66,18.38 v1(34.35,18.38) ; C36.2 34.21,17.72 ; U11.45 45.68,55.42 v1(45.4,55.69) ; v1(44.39,51.63) 44.61,51.4 U11.34 ; 24.92,61.49 J6.3 23.34,59.92 ; v1(22.86,56.13) 22.75,56.02 U10.3 22.13,56.51 ; 1.75,1.75 J15.43 3.33,3.33 ; v1(18.67,42.93) 18.28,43.32 U20.8 17.14,42.86 ; v1(22.29,52.83) 21.84,52.39 C14.2 ; 42.37,43.31 C20.2 ; C20.2 43.49,43.31 ; C20.2 42.93,43.87 ; U22.H6 v1(34.98,39.57) ; U22.J9 v1(35.78,42.77) ; 27.41,21.79 U28.15 27.41,24.28 v1(27.18,24.51) ; 51.12,70.85 C2.2 v1(51.82,70.29) ; FL1.5 v1(45.22,8.7) ; v1(21.4,19.11) 21.71,18.8 U30.25 21.15,17.77 ; 53.69,68.8 Q2.2 54.2,68.36 54.42,68.14 v1(54.74,68.14) ; C42.2 v1(45.02,6.35) ; U22.E7 v1(31.78,41.17) ; J2.5 46.29,71.06 v1(45.85,70.61) ; v1(40.58,54.48) 40.13,54.48 40.06,54.42 U11.18 ; v1(50.1,20.45) R102.2 C32.2 49.96,21.34 ; v1(15.43,65.41) C4.2 14.87,64.71 ; 16.89,51.18 U15.9 16.89,49.28 ; v1(51.82,69.34) R6.2 51.12,68.78 ; 63.19,67.96 J21.1 61.71,66.48 ; v1(50.16,25.65) C31.2 50.72,24.89 ; 29.5,5.72 U30.2 ; U30.2 32,5.72 v1(32,5.71) ; U30.2 30.66,6.27 ; 54.19,46.35 U39.3 53.69,47.47 53.51,47.65 v1(53.44,47.65) ; C41.2 v1(33.66,10.16) ; C41.2 33.1,10.86 ; C41.2 34.21,10.86 ; 5.87,3.33 J15.44 4.29,1.75 ; U22.F8 v1(32.58,41.97) ; v1(55.09,74.57) 55.87,73.79 R123.2 55.88,74.35 ; U22.J11 v1(35.78,43.57) U22.J10 ; U38.2 30.05,32.24 v1(29.57,31.77) ; U10.2 v1(22.86,55.37) ; 30.65,71.97 J1.6 31.45,71.07 ; 17.97,60.02 C8.2 17.97,61.28 v1(17.84,61.4) U7.B1 ; v1(29.21,4.93) 29.3,5.02 U30.1 31.94,5.02 v1(32,4.95) ; 49.45,30.04 U27.2 51.18,30.04 51.44,29.78 v1(51.44,29.59) ; U12.7 11.82,53.08 v1(11.81,53.09) ; v1(15.88,30.99) 15.89,30.99 15.89,31.13 U23.8 ; U19.8 18.28,37.22 v1(18.67,36.83) ; U19.8 17.14,36.76 ; U19.8 15.95,37.22 ; v1(52.91,65.48) 52.59,65.48 52.26,65.15 U6.2 ; U22.L8 v1(37.38,41.97) U22.M9 ; U22.A1 28.98,35.97 v1(28.58,35.57) ; C3.2 v1(51.69,68.14) ; v1(40.51,69.98) 40.23,69.69 Q5.2 39.72,69.19 ; U33.2 25.69,32.24 25.41,31.96 25.41,30.92 v1(25.27,30.78) ; v1(21.53,49.05) C15.2 20.97,49.72 ; U22.M1 v1(38.18,35.57) ; v1(49.53,62.61) C6.2 48.84,61.66 ; 1.75,34.77 J15.17 3.33,36.35 ; 11.03,50.86 v1(12.07,50.86) ; 59.12,71.26 U2.7 59.12,68.9 v1(59.18,68.83) ; v1(43.61,7.54) 43.97,7.9 FL1.3 ; 41.75,69.19 Q4.2 42.13,69.69 v1(42.42,69.98) ; C39.2 46.74,13.02 v1(46.16,13.02) RF1.2 44.41,13.02 ; U12.3 12.31,48.84 v1(12.57,48.58) 12.82,48.82 U12.4 13.27,49.44 ; 34.86,53.86 C70.2 35.42,54.42 ; 44.27,31.46 U21.2 44.27,32.68 ; C22.2 v1(53.85,35.05) ; v1(19.69,5) 19.7,5.02 U30.42 22.41,5.02 v1(22.48,4.95) ; C14.2 21.53,52.95 ; C14.2 20.97,52.39 ; Y4.2 38.32,14.48 v1(37.4,14.48) 37.4,15.24 36.84,15.24 ; 65.25,50.01 J14.12 66.83,51.59 ; v1(30.8,67.12) U5.2 30.8,69.11 ; 53.15,32.46 C24.2 v1(53.85,33.02) ; 45.58,40 44.83,40 44.83,39.23 ; U22.M7 v1(38.18,41.17) ; 21.21,54.37 U10.7 v1(21.21,56.52) ; U22.A12 v1(28.58,45.17) ; U22.F7 v1(32.58,41.17) ; J10.5 17.84,21.27 ; U22.J12 35.38,45.01 v1(35.12,45.28) ; v1(24.64,41.78) 23.98,41.12 U19.15 ; v1(55.5,52.07) 55.82,52.39 C13.2 56.38,52.83 ; U22.J6 v1(35.78,39.57) ; R87.2 v1(44.07,25.65) ; 62.73,70.14 U36.2 ; 15.46,49.02 U15.4 ; U22.L3 v1(37.38,37.17) ; U22.J8 v1(35.78,41.97)
  TOP w0.305: v1(46.55,49.09) 45.97,48.51 C102.2
  TOP w0.508: C12.2 C10.2
  LAYER2_GND w0.254: 64.27,51.57 J14.11 62.73,50.03 ; 30.28,73.54 J1.11 29.43,74.75 ; 45.17,72.85 J2.6 45.17,71.1 ; 44,73.54 J2.11 43.14,74.75 ; 35.65,7.71 J20.1 34.2,6.26 ; 1.77,1.77 J15.43 3.31,3.31 ; 50.34,74.75 J2.8 51.19,73.54 ; 17.23,7.19 SW4.5 18.59,8.55 ; 66.81,16.01 65.27,14.47 ; 31.45,71.1 J1.6 31.45,72.85 ; 9.52,24.76 J9.7 10.8,26.04 ; 3.31,36.33 J15.17 1.77,34.79 ; 65.27,50.03 J14.12 66.81,51.57 ; 63.18,67.95 J21.1 61.73,66.5 ; 59.06,42.81 57.78,41.52 ; 36.63,74.75 J1.8 37.48,73.54 ; 9.52,27.3 10.8,28.58 ; 5.85,36.33 J15.18 4.31,34.79 ; 24.9,61.48 J6.3 23.36,59.94 ; 5.85,3.31 J15.44 4.31,1.77 ; 24.63,73.65 J4.1 22.92,71.93 ; 36.3,71.1 J1.7 36.3,72.85 ; 50.02,72.85 J2.7 50.02,71.1 ; 64.27,23.63 62.73,22.09
  BOTTOM w0.127: U31.3 v1(66.98,72.27) 66.65,71.95 U31.5
  BOTTOM w0.203: U32.4 64.66,69.26 v1(64.64,69.28)
  BOTTOM w0.254: 39.94,40.84 C78.2 ; C78.2 40.5,41.4 ; C78.2 39.94,41.97 v1(39.88,42.04) ; 57.78,41.52 59.06,42.81 ; 44.95,54.8 C61.2 v1(44.39,54.04) ; R257.2 v1(22.67,8.76) ; R257.2 21.84,8.2 ; R257.2 21.84,9.32 ; 44.26,27.7 C100.2 44.77,28.26 v1(45.09,28.57) ; 1.77,1.77 J15.43 3.31,3.31 ; 35.25,64.14 C53.2 v1(35.81,63.31) ; 22.63,71.65 J4.1 24.92,73.93 ; C68.2 v1(67.5,68.58) ; C69.2 44.26,51.5 v1(44.39,51.63) ; C69.2 44.82,50.86 ; C69.2 44.26,50.3 ; C103.2 v1(63.63,75.31) ; C103.2 64.19,74.68 ; C103.2 63.59,74.64 Q1.2 ; 41.8,54.8 C62.2 v1(42.35,54.1) ; 10.8,26.04 J9.7 9.52,24.76 ; 30.43,65.41 C51.2 30.99,64.64 v1(30.92,64.58) R141.2 31.48,63.82 ; C86.2 48.88,35.94 ; C86.2 47.76,35.94 ; C86.2 48.32,36.5 ; v1(10.16,52.26) 9.97,52.45 R280.2 9.14,51.89 ; C66.2 34.21,57.53 ; C66.2 33.66,58.61 v1(33.72,58.67) ; C66.2 33.1,57.53 ; v1(61.41,72.34) 61.46,72.39 61.83,72.39 61.88,72.44 62.27,72.44 62.32,72.39 R122.2 ; C89.2 28.89,32.31 ; C89.2 28.91,31.77 v1(29.57,31.77) ; C89.2 28.89,31.19 ; C89.2 29.45,31.75 ; 37.72,34.24 C88.2 ; C88.2 38.28,34.8 ; C88.2 38.18,35.26 v1(38.18,35.57) ; 66.81,51.57 J14.12 65.27,50.03 ; v1(51.69,50.16) 51.4,50.46 51.4,50.49 51.31,50.58 C16.2 ; v1(35.78,36.37) 35.77,36.39 C85.2 34.49,36.39 ; v1(60.96,73.41) 61.66,73.41 C45.2 61.72,72.91 ; 16.76,48.57 R188.2 v1(15.62,48.01) ; v1(33.18,61.38) 32.64,60.84 32.64,59.94 33.2,59.94 ; 35.19,41.27 R199.2 35.75,41.94 v1(35.78,41.97) ; 39.76,36.2 C25.2 40.32,35.47 v1(40.72,35.08) ; v1(39.12,34.8) C84.2 39.68,35.56 ; 56.01,55.63 56.01,54.86 55.75,54.61 ; 56.01,55.63 56.01,56.19 ; 56.01,55.63 55.45,55.63 ; 56.01,57.02 55.25,57.02 v1(54.86,56.64) ; 56.01,57.02 56.01,57.58 ; 56.01,57.02 56.01,56.46 ; C92.2 52.2,32.82 ; C92.2 C93.2 52.2,30.81 ; C92.2 51.75,32.26 v1(51.44,31.94) ; v1(10.87,59.48) 10.87,60.18 R142.2 ; 41.27,39.68 C63.2 41.27,38.56 ; v1(51.44,29.59) 51.44,29.87 51.27,30.04 C90.2 ; 35.65,7.71 J20.1 34.2,6.26 ; 64.27,51.57 J14.11 62.73,50.03 ; C16.2 51.31,51.87 ; C16.2 50.56,51.18 ; 38.72,49.97 C75.2 38.16,50.53 ; 62.73,22.09 64.27,23.63 ; C98.2 43.12,46.16 v1(43.12,46.29) ; 37.48,73.54 J1.8 36.63,74.75 ; 43.14,74.75 J2.11 44,73.54 ; 45.17,72.85 J2.6 45.17,71.1 ; C94.2 31.8,9.02 ; C94.2 31.24,8.5 31.11,8.37 30.69,8.37 v1(30.5,8.57) ; C94.2 30.68,9.02 ; 51.19,73.54 J2.8 50.34,74.75 ; 34.73,32.08 R283.2 35.29,32.64 ; v1(45.4,55.69) C59.2 46.55,55.13 ; 40.33,31.62 C91.2 ; C91.2 40.89,31.06 ; C91.2 41.45,31.62 ; 10.8,28.58 9.52,27.3 ; C67.2 62.67,69.98 v1(62.17,69.47) 61.72,69.91 C48.2 61.16,70.29 ; 40.83,63.89 C104.2 41.39,64.45 ; v1(30.8,67.12) 30.8,66.55 C50.2 ; 47.13,52.64 C65.2 ; C65.2 47.69,52.08 ; C65.2 48.32,52.64 v1(48.51,52.45) ; 31.45,71.1 J1.6 31.45,72.85 ; v1(10.1,53.59) 9.97,53.72 C97.2 ; v1(39.07,37.81) 39.05,37.81 R262.1 ; 19.94,50.22 C29.2 20.5,50.77 ; 24.9,61.48 J6.3 23.36,59.94 ; C90.2 50.74,29.48 ; C90.2 50.18,30.04 ; 39.05,42.75 R192.2 39.51,43.31 v1(39.83,42.99) ; v1(35.78,39.57) 35.81,39.54 C82.2 ; 53.78,60.85 C54.2 ; C54.2 53.78,61.96 ; C54.2 54.34,61.4 ; R11.2 36.31,68.07 ; R11.2 35.19,68.07 ; R11.2 35.75,67.51 ; 18.59,8.55 SW4.5 17.23,7.19 ; C17.2 44.5,47.24 ; C17.2 43.38,47.24 ; C17.2 43.94,47.8 ; 30.3,59.94 30.86,59.94 30.86,61.09 v1(30.48,61.47) ; v1(38.18,41.17) 38.08,41.27 C81.2 37.53,41.83 ; 39.18,55.13 R148.2 v1(40.32,55.69) ; 40.51,41.73 C77.2 ; C77.2 39.95,42.29 ; C77.2 41.07,42.29 ; v1(36.83,63.31) C52.2 37.39,64.14 ; 49.02,45.35 C73.2 49.02,46.67 v1(49.09,46.74) ; v1(22.86,7.62) 22.48,7.24 C95.2 ; 39.75,63.89 C105.2 39.19,64.45 ; 38.29,57.26 C58.2 v1(37.27,56.71) ; 49.29,47.62 C71.2 ; C71.2 50.41,47.62 ; C71.2 50.23,48.01 v1(50.6,48.01) ; C71.2 49.85,48.18 ; C95.2 21.84,7.8 ; C95.2 21.84,6.68 ; 20.57,53.77 C64.2 19.56,53.21 19.11,53.66 v1(19.11,53.87) ; 36.65,49.97 R171.2 37.21,50.53 ; 5.85,36.33 J15.18 4.31,34.79 ; 3.31,36.33 J15.17 1.77,34.79 ; C76.2 50.22,37.34 ; C76.2 49.1,37.34 ; C76.2 49.66,36.78 ; 66.81,16.01 65.27,14.47 ; v1(53.44,47.65) 53.44,47.7 52.88,48.26 C96.2 ; 38.28,46.99 C74.2 37.72,47.55 ; C50.2 30.99,66.92 ; C50.2 30.43,66.36 ; 59.12,74.98 C44.2 C46.2 v1(59.12,72.25) ; 29.43,74.75 J1.11 30.28,73.54 ; v1(31.78,41.17) 31.76,41.14 C79.2 31.2,40.38 ; v1(59.18,68.83) 59.12,68.9 C49.2 C47.2 59.12,71.68 ; 50.02,71.1 J2.7 50.02,72.85 ; R284.2 v1(49.4,49.34) ; R284.2 50.1,49.9 ; R284.2 50.1,48.78 ; 47.64,42.48 C9.2 ; C9.2 48.2,41.92 ; C9.2 48.2,43.04 ; v1(37.38,37.17) 38.03,37.17 C83.2 ; 48.18,31.88 C99.2 47.62,33.66 v1(47.75,33.78) ; C28.2 12.7,52.3 ; C28.2 12.14,52.86 ; C28.2 12.14,51.74 ; 61.73,66.5 J21.1 63.18,67.95 ; C80.2 v1(45.91,30.61) ; v1(37.27,54.86) 37.53,54.61 R151.2 38.66,54.61 ; 46.18,29.53 C72.2 47.3,29.53 ; 36.3,72.85 J1.7 36.3,71.1 ; R146.2 v1(54.86,59.56) ; C18.2 v1(44.2,44.77) ; 43.37,27.44 R204.2 42.67,28 v1(42.67,28.45) ; 4.31,1.77 J15.44 5.85,3.31 ; 49.45,45.06 R167.2
  BOTTOM w0.381: v1(46.76,30.26) 46.74,30.24 C72.2
  vias: v1(0.76,72.39) v1(0.76,69.85) v1(0.76,67.31) v1(0.76,64.77) v1(0.76,62.61) v1(0.76,59.69) v1(0.76,57.15) v1(0.76,54.61) v1(0.76,52.07) v1(0.76,49.53) v1(0.76,46.99) v1(0.76,44.45) v1(0.76,41.91) v1(0.76,39.37) v1(0.76,36.83) v1(0.76,34.29) v1(0.76,31.75) v1(0.76,29.21) v1(0.76,26.67) v1(0.76,24.13) v1(0.76,21.59) v1(0.76,19.05) v1(0.76,16.51) v1(0.76,13.97) v1(0.76,11.43) v1(0.76,8.89) v1(0.76,6.35) v1(0.79,3.78) v1(0.89,74.93) v1(1.8,0.89) v1(2.82,0.89) v1(3.84,0.89) v1(4.33,75.36) v1(4.85,0.89) v1(5.87,0.89) v1(6.88,0.89) v1(6.95,75.33) v1(7.49,62.99) v1(8.03,0.89) v1(9.3,0.89) v1(9.82,75.38) v1(10.57,0.89) v1(11.84,0.89) v1(12.18,75.38) v1(12.4,59.48) v1(14.72,75.38) v1(16.01,73.82) v1(16.89,50.1) v1(17.26,75.38) v1(18.67,4.95) v1(19.8,75.38) v1(21.01,73.61) v1(22.34,75.38) v1(23.75,4.95) v1(24.38,5.97) v1(24.88,75.38) v1(25.91,73.79) v1(25.91,6) v1(26.67,4.93) v1(26.86,75.37) v1(27.94,4.95) v1(29.46,57.28) v1(29.92,70.81) v1(31.88,70.74) v1(32.38,50.86) v1(32.73,74.75) v1(33.4,4.95) v1(34.16,51.82) v1(35.03,74.75) v1(35.28,61.45) v1(35.41,28.42) v1(35.56,54.42) v1(35.81,20.32) v1(35.81,14.35) v1(35.9,26.96) v1(35.94,23.24) v1(35.94,17.27) v1(35.9,10.63) v1(35.94,4.95) v1(36.35,28.42) v1(36.96,58.55) v1(37.17,20.22) v1(37.59,4.98) v1(38.93,49.97) v1(39.5,27.05) v1(39.62,10.54) v1(41.33,60.12) v1(41.4,29.85) v1(41.57,31.69) v1(42.36,7.82) v1(42.36,5.9) v1(42.55,27.05) v1(42.55,10.54) v1(43.12,72.14) v1(43.18,18.92) v1(43.18,16.64) v1(43.52,59.79) v1(44.01,43.43) v1(44.32,17.78) v1(45.4,36.7) v1(45.47,27.05) v1(45.47,18.92) v1(45.47,16.64) v1(45.59,10.54) v1(45.97,11.77) v1(46.44,74.75) v1(46.98,60.43) v1(47.26,10.6) v1(47.48,11.92) v1(47.41,9.55) v1(47.41,8.52) v1(47.4,7.55) v1(47.56,6.48) v1(47.5,5.46) v1(48.48,27.01) v1(48.51,5.08) v1(48.68,60.19) v1(48.75,74.75) v1(48.77,10.54) v1(49.09,35.94) v1(49.34,14.39) v1(49.53,5.08) v1(50.63,5.72) v1(51.62,6.51) v1(52.04,26.92) v1(52.2,10.54) v1(52.32,23.24) v1(52.32,20.19) v1(52.32,17.4) v1(52.32,14.22) v1(52.84,7.02) v1(54.67,60.83) v1(55.25,54.93) v1(56.01,75.31) v1(56.64,1.02) v1(58.55,75.31) v1(58.67,1.02) v1(59.99,12.22) v1(60.07,10.1) v1(60.71,1.02) v1(60.9,68.07) v1(61.09,75.31) v1(61.61,17.79) v1(62.74,0.86) v1(64.77,0.86) v1(64.8,64.64) v1(66.17,75.31) v1(67.5,74.93) v1(67.62,71.53) v1(67.78,64.77) v1(67.78,62.23) v1(67.78,59.69) v1(67.78,57.15) v1(67.78,54.61) v1(67.78,52.07) v1(67.78,49.53) v1(67.78,46.99) v1(67.78,44.45) v1(67.78,41.91) v1(67.78,39.37) v1(67.78,36.83) v1(67.78,34.29) v1(67.78,31.75) v1(67.78,26.67) v1(67.78,24.13) v1(67.72,21.59) v1(67.72,19.05) v1(67.78,16.45) v1(67.72,13.91) v1(67.78,11.4) v1(67.78,8.86) v1(67.78,6.32) v1(67.84,29.21) v1(67.8,3.89)
VBAT_SOC: length 3
  TOP w0.254: U22.K2 36.19,36.77 v1(36.59,36.37) ; U22.L1 36.99,35.97 v1(37.39,35.57) ; U22.M2 37.78,36.77 v1(37.39,36.37) 36.99,36.77 U22.L2
  BOTTOM w0.381: v1(37.39,36.37) 38.13,36.37 C83.1
  vias: v1(38.23,31.31)
VCC_ADC: length 23.4
  TOP w0.381: v1(40.51,43.81) 40.45,43.75 38.37,43.75 U22.M10
  TOP w0.508: v1(52.71,40) 52.71,38.48 52.2,37.97 C23.1 51.05,37.08 50.37,37.77 FB16.2
  L3_SIG w0.508: v1(52.71,40) 52.45,40.26 52.45,41.4 v1(52.01,41.85)
  L4_SIG w0.508: v1(52.01,41.85) 50.16,41.85 49.21,42.8 41.53,42.8 v1(40.51,43.81)
  BOTTOM w0.381: C77.1 40.51,43.75 v1(40.51,43.81)
VCC_AON_1P8: length 25
  TOP w0.254: U22.J4 35.38,38.37 v1(34.98,37.97) 34.58,38.37 U22.H4 ; v1(53.72,30.23) 53.72,30.47 53.21,30.99 U27.5 ; U22.J5 35.38,39.17 v1(34.98,38.77) U22.H5
  L4_SIG w0.508: v1(37.31,30.61) 43.49,30.61 44.76,31.88 48.96,31.88 50.61,30.23 v1(53.72,30.23)
  BOTTOM w0.381: v1(34.98,38.77) v1(34.98,37.97) 34.99,37.97 C82.1 ; v1(53.72,30.23) 53.09,30.86 C93.1 C92.1
VCC_AON_EN: length 2.2
  TOP w0.254: U27.3 51.05,29.09 v1(51.44,28.7)
  BOTTOM w0.381: v1(51.44,28.7) 51.82,29.08 R215.2
VCC_ARD_USB_5V: length 74.9
  TOP w0.508: D6.1 21.34,64.83 v1(20.76,64.26) ; v1(6.98,31.12) 7.43,31.56 10.61,31.56 10.92,31.24 13.46,31.24 13.84,30.86 FB12.1 ; v1(19.43,64.26) 19.49,64.33 D7.1
  L3_SIG w0.508: v1(17.4,57.28) 20.45,57.28 20.95,57.78 20.95,60.13 19.43,61.66 v1(19.43,64.26) ; v1(14.03,56.13) 10.35,56.13 6.83,52.62 6.83,35.14 6.98,34.99 v1(6.98,31.12)
  L4_SIG w0.508: v1(14.03,56.13) 14.86,56.13 16,57.28 v1(17.4,57.28)
  BOTTOM w0.508: J5.1 10.05,69.58 12.84,69.58 14.61,67.82 14.61,64.52 17.02,62.1 18.92,62.1 19.43,62.61 v1(19.43,64.26) v1(20.76,64.26)
VCC_AVD_OPM_2P6: length 3.6
  TOP w0.254: U22.K1 v1(36.58,35.57) ; U22.J1 v1(35.78,35.57)
  BOTTOM w0.381: C88.1 36.58,35.04 v1(36.58,35.57) v1(35.78,35.57) 35.71,35.5 C85.1
VCC_CMP: length 24.5
  TOP w0.381: U22.M8 37.9,41.69 38.4,41.69 39.43,40.65 v1(39.43,40.64) ; R272.2 50.1,40.32 v1(50.67,39.75)
  TOP w0.508: R64.1 v1(51.5,33.02) C24.1
  L3_SIG w0.508: v1(50.67,39.75) 50.67,33.85 v1(51.5,33.02)
  L4_SIG w0.508: v1(50.67,39.75) 50.19,40.23 39.84,40.23 v1(39.43,40.64)
  BOTTOM w0.381: C78.1 39.05,41.02 v1(39.43,40.64)
VCC_EX_HOST_1P8: length 64.7
  TOP w0.508: R10.1 v1(17.21,65.41) ; FB8.2 v1(49.09,41.78)
  L3_SIG w0.508: v1(17.21,65.41) 17.84,66.04 19.3,66.04 20.13,65.21 20.13,62.29 21.72,60.71 v1(21.72,58.04) ; v1(50.67,59.94) 50.67,52.39 50.01,51.73 50.01,44.86 50.18,44.69 50.18,42.88 v1(49.09,41.78)
  L4_SIG w0.508: v1(50.67,59.94) 49.54,59.94 49.2,59.6 46.57,59.6 45.46,60.71 40.4,60.71 39,59.31 30.23,59.31 29.78,58.86 22.54,58.86 v1(21.72,58.04)
  BOTTOM w0.381: C9.1 v1(49.09,41.78)
VCC_EX_PLT_1P8: length 12.1
  TOP w0.381: v1(48.77,27.94) 48.37,28.33 U8.3
  TOP w0.508: v1(49.02,35.05) 46.23,35.05 FB9.2
  BOTTOM w0.381: v1(48.77,27.94) 49.38,28.55 49.38,32.97 49.5,33.1 49.5,34.57 v1(49.02,35.05) C86.1
VCC_EX_PLT_3P3: length 14.1
  TOP w0.381: U18.3 48.37,31.6 49.57,31.6 v1(49.91,31.94) R64.2
  TOP w0.508: FB7.2 45.4,38.23 v1(48.96,38.23)
  L3_SIG w0.508: v1(48.96,38.23) 49.91,37.27 v1(49.91,31.94)
  BOTTOM w0.381: C76.1 v1(48.96,38.23)
VCC_HOST_1P8: length 18.2
  TOP w0.254: U22.J7 v1(35.78,40.37) ; U22.K6 36.18,39.97 v1(36.58,39.57) ; U22.H7 v1(34.98,40.37) ; v1(37.38,39.57) 36.98,39.97 U22.L6 ; U22.K7 36.18,40.77 v1(36.58,40.37) U22.L7
  TOP w0.381: R5.1 v1(46.74,48.45)
  BOTTOM w0.381: v1(37.38,39.57) 37.53,39.71 C81.1 ; v1(34.98,40.37) v1(35.78,40.37) v1(36.58,40.37) 37.51,40.37 C81.1 ; v1(46.74,48.45) R5.1 45.21,46.1 45.21,43.43 v1(43.88,42.1) ; C81.1 38.67,40.39 39.18,39.88 40.01,39.88 R213.1
  vias: v1(42.48,41.53)
VCC_HOST_1P8_IND: length 4.6
  TOP w0.381: L4.1 40.82,41.08 39.71,39.97 U22.M6
VCC_IO: length 102.5
  TOP w0.203: v1(32,54.86) 32.36,55.22 33.18,55.22 33.33,55.36 U13.2 ; v1(50.67,45.85) 50.36,46.16 U17.2 ; U9.2 57.6,56.44 57.91,56.13 v1(57.91,55.44) ; v1(22.35,53.59) 22.35,54.5 U10.1
  TOP w0.254: U19.16 22.38,41.77 22.31,41.84 v1(22.31,42.71) ; U23.16 21.6,35.68 v1(21.46,35.81) ; v1(19.18,51.75) 19.18,51.66 18.5,50.98 U15.8 ; v1(28.19,24.51) 28.06,24.37 U28.16 ; U25.16 34.15,24.37 v1(34.29,24.51) ; U12.8 11.31,52.69 v1(10.92,53.09) ; U20.16 20.9,47.87 v1(20.83,47.8)
  TOP w0.305: v1(44.26,29.85) 44.27,29.85 U21.5
  TOP w0.381: v1(32,54.86) 32.45,54.42 C70.1 ; v1(29.53,32.51) 29.26,32.24 U33.5 ; FB6.1 v1(20.26,49.28) ; R52.1 v1(13.91,38.48) ; U36.6 62.08,71.89 v1(62.07,71.88) ; J10.1 15.3,21.65 v1(14.92,21.27) ; FB15.1 v1(37.66,13.14) ; U38.5 32.43,32.24 v1(31.94,31.75) ; FB14.1 v1(31.37,20.57)
  TOP w0.508: R66.2 v1(51.5,34.04) C26.1
  L3_SIG w0.203: v1(37.66,13.14) 38.35,12.45 38.35,9.4 v1(37.85,8.89)
  L4_SIG w0.381: v1(66.8,70.87) 65.79,71.88 v1(62.07,71.88) 62.07,71.28 61.49,70.7 59.35,70.7 v1(58.1,71.95)
  BOTTOM w0.203: U32.8 66.31,70.38 v1(66.8,70.87) ; v1(19.71,12.36) 20.05,12.7 21.31,12.7 21.33,12.71 R246.1
  BOTTOM w0.381: R187.1 v1(15.62,38.86) ; R209.1 v1(31.94,31.75) R282.1 ; R211.1 29.02,33.02 v1(29.53,32.51) 29.97,32.96 R210.1 ; R137.1 v1(38.35,69.09) ; R206.1 26.42,36.64 v1(25.97,37.08) ; R206.1 R205.1 ; R206.1 26.67,36.13 R207.1 ; R203.1 C80.1 v1(44.26,29.85) ; R173.1 R172.1 v1(34.86,50.11) ; C29.1 19.85,51.75 v1(19.18,51.75) ; R180.1 R179.1 R178.1 v1(29.46,48.26) ; R152.1 v1(27.62,55.24) ; v1(32,54.86) 32.51,55.37 R129.1 ; v1(32.51,48.26) R175.1 R174.1 ; R189.1 v1(15.62,45.97) ; R185.1 v1(26.04,45.34) ; C60.1 57.72,55.63 v1(57.91,55.44) ; C73.1 50.61,45.91 v1(50.67,45.85) ; R134.1 v1(43.43,69.09) ; C89.1 27.44,32.31 v1(27.44,32.52) 27.56,32.64 R212.1 ; R202.1 v1(26.04,39.24) ; R165.1 R159.1 v1(17.27,51.75) 18.22,51.75 R163.1 ; R277.1 48.23,46.57 v1(47.56,47.24) ; R193.1 R190.1 v1(26.04,44.32) ; R275.1 v1(31.75,61.47) ; R176.1 R177.1 v1(30.48,48.26) ; v1(62.07,71.88) 62.67,71.28 C67.1 ; C28.1 11.25,52.76 v1(10.92,53.09) ; R201.1 v1(26.04,40.26) ; v1(22.54,16) R237.1 R232.1 ; R150.1 20.32,54.41 v1(19.77,53.86) ; R157.1 R153.1 v1(17.34,54.24) ; R194.1 v1(26.04,42.29) ; C68.1 67.06,70.87 v1(66.8,70.87) ; v1(42.23,31.69) 42.48,31.94 R197.1 ; R249.1 R246.1 ; R191.1 v1(15.62,40.89) ; C64.1 21.72,53.21 22.1,53.59 v1(22.35,53.59) ; R200.1 v1(26.04,41.27) ; R182.1 R181.1 26.48,47.94 v1(26.16,48.26) ; R170.1 v1(40.39,48.26)
VCC_IO_AON: length 46.6
  TOP w0.152: U26.4 45.01,48.2 C102.1
  TOP w0.254: U22.F6 v1(32.59,39.57) ; U22.H10 v1(34.98,43.57) ; U22.G8 v1(34.18,41.97)
  TOP w0.381: C102.1 44.77,48.64 v1(44.45,48.64)
  TOP w0.508: C22.1 v1(51.56,35.05) R57.2
  L3_SIG w0.381: v1(50.93,50.29) 50.93,48.58 51.62,47.88 51.62,45.97 50.91,45.26 50.91,41.26 51.56,40.61 v1(51.56,35.05)
  L4_SIG w0.381: v1(50.93,50.29) 50.56,49.92 45.73,49.92 v1(44.45,48.64) 43.17,49.92 40.31,49.92 39.31,50.93 v1(34.16,50.93)
  BOTTOM w0.381: 33.65,43.99 33.65,45.66 34.14,46.15 34.14,46.26 34.16,46.28 v1(34.16,50.93)
VCC_PLT: length 8.7
  TOP w0.381: v1(48.79,30.26) 48.79,29.93 U8.6 ; U18.6 48.37,32.72 v1(48.97,33.32)
  TOP w0.508: FB16.1 49.91,35.94 R57.1 R66.1 49.69,34.04 v1(48.97,33.32)
  BOTTOM w0.381: v1(48.97,33.32) 48.79,33.13 v1(48.79,30.26)
VCC_PLT_1P8: length 2.6
  TOP w0.254: v1(37.38,37.97) 36.98,38.37 U22.L4 ; U22.K4 v1(36.58,37.97)
  TOP w0.381: C87.1 FB9.1
  vias: v1(42.16,34.99) v1(42.74,36.7)
VCC_PLT_1P8_IND: length 4.7
  TOP w0.381: L6.1 40.82,37.41 39.86,38.37 U22.M4
VCC_PLT_3P3: length 3.4
  TOP w0.254: v1(37.38,38.77) 36.98,39.17 U22.L5 ; U22.K5 v1(36.58,38.77)
  BOTTOM w0.381: C63.1 v1(42.86,39.12) v1(43.62,39.12) ; v1(37.38,38.77) v1(36.58,38.77)
VCC_PLT_3P3_IND: length 3.3
  TOP w0.381: L5.1 40.6,38.89 38.06,38.89 U22.M5
VCC_RADIO: length 9.7
  TOP w0.381: FB15.2 38.99,12.19 v1(40.64,12.19) R113.1 ; R114.1 48.01,12.57 v1(48.51,12.07) ; v1(41.02,23.3) R99.1 ; v1(43.94,23.24) R101.1 ; R107.1 v1(38.23,18.35) ; R88.1 v1(45.09,25.65) ; C31.1 v1(50.16,23.24) ; v1(42.04,23.3) R100.1 ; R84.1 v1(39.43,25.65) ; R106.1 v1(50.16,18.67)
VCC_RST_GEN: length 4
  BOTTOM w0.127: U31.4 66.95,71.62 67.44,72.11 67.44,72.54 66.76,73.22 R125.2
VCC_USB_3P3: length 11.1
  TOP w0.381: U22.L12 v1(36.98,45.32)
  L4_SIG w0.381: v1(36.98,45.32) 37.71,46.05 40.75,46.05 42.23,44.58 v1(42.48,44.58)
  BOTTOM w0.203: v1(36.98,45.32) 36.83,45.48 R278.1 C74.1
  BOTTOM w0.381: C17.1 43.31,45.72 C18.1 43.31,45.34 42.55,44.58 v1(42.48,44.58)
VCCOUT_AON_1P8: length 28.7
  TOP w0.381: v1(38.87,37.18) 38.17,37.18 U22.M3
  L3_SIG w0.508: v1(53.92,29.08) 53.14,29.87 53.14,37.39 v1(53.56,37.81)
  L4_SIG w0.508: v1(53.56,37.81) 53.09,37.34 40.89,37.34 40.58,37.02 39.03,37.02 v1(38.87,37.18)
  BOTTOM w0.381: R215.1 v1(53.92,29.08) ; C84.1 38.87,36.7 v1(38.87,37.18) 40.22,37.18 C25.1
VDD_ARDUINO: length 133.8
  TOP w0.381: R126.1 55.56,72.77 v1(55.05,73.28) ; v1(49.59,43.43) 50.1,42.93 R272.1 ; v1(57.45,74.1) 57.72,74.1 57.74,74.08 U1.1
  TOP w0.508: FB10.1 v1(14.73,33.15)
  L3_SIG w0.381: v1(49.59,43.43) 48.77,44.26 48.77,46.32 48.56,46.52 48.56,49.96 49.15,50.55 49.15,55.37 50.04,56.26 50.04,60.2 51.09,61.25 51.09,63.98 50.85,64.22 50.85,65.96 51.45,66.56 52.44,66.56 52.97,67.09 52.97,71.62 v1(52.45,72.14)
  L4_SIG w0.508: v1(52.45,72.14) 52.44,72.15 ; 52.44,72.15 53.93,72.15 v1(55.05,73.28) 56.26,73.28 57.09,74.1 v1(57.45,74.1) ; 52.44,72.15 51.83,72.15 50.1,70.42 47.94,70.42 46.98,69.46 45.54,69.46 45.18,69.82 43.27,69.82 42.74,69.28 39.56,69.28 39.12,69.72 36.77,69.72 36.03,70.45 33.37,70.45 32.9,69.98 27.52,69.98 25.73,68.18 15.67,68.18 14.8,67.31 14.8,63.5 15.18,63.12 15.18,58.29 13.84,56.96 11.18,56.96 6.85,52.63 6.85,32.8 7.84,31.81 13.4,31.81 v1(14.73,33.15)
  BOTTOM w0.381: v1(57.45,74.1) 57.53,74.1 57.85,74.42 C44.1 C46.1
VDD_ARDUINO_EN: length 2.1
  TOP w0.127: U1.4 60.81,72.78 v1(60.87,72.72)
  BOTTOM w0.127: v1(60.87,72.72) 60.82,72.77 60.2,72.77 R124.2
VDD_ARDUINO_FB: length 2.4
  TOP w0.127: R123.1 R126.2 56.91,72.78 U1.3
VDD_HDR: length 51.3
  TOP w0.381: U2.1 57.75,70.8 57.61,70.94 57.58,70.94 v1(57.4,71.12) ; R132.1 v1(55.12,69.98)
  L3_SIG w0.254: 66.04,2.54 66.04,3.61 ; 66.04,2.54 67.21,2.54 ; 66.04,2.54 64.97,2.54 ; 66.04,2.54 66.04,1.37 ; 66.04,34.09 66.04,31.95 ; 5.08,14.17 J15.34 5.08,16.31 ; 2.54,56.95 J15.1 2.54,54.81 ; 66.04,62.43 J14.2 66.04,64.57 ; 5.08,54.81 J15.2 5.08,56.95 ; 63.5,34.49 63.5,36.63 ; 63.5,2.54 63.5,1.32 ; 63.5,2.54 64.57,2.54 ; 63.5,2.54 63.5,3.61 ; 63.5,2.54 62.2,2.54 ; 2.54,21.39 J15.29 2.54,19.25 ; 63.5,62.43 J14.1 63.5,64.57
  LAYER5_PWR w0.254: 1.77,19.55 J15.29 3.31,21.09 ; 62.73,1.77 64.27,3.31 ; 65.27,32.25 66.81,33.79 ; 64.27,36.33 62.73,34.79 ; 5.85,16.01 J15.34 4.31,14.47 ; 4.31,55.11 J15.2 5.85,56.65 ; 66.81,64.27 J14.2 65.27,62.73 ; 3.31,56.65 J15.1 1.77,55.11 ; 66.81,3.31 65.27,1.77 ; 64.27,64.27 J14.1 62.73,62.73
  BOTTOM w0.381: C49.1 C47.1 v1(57.4,71.12)
